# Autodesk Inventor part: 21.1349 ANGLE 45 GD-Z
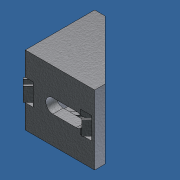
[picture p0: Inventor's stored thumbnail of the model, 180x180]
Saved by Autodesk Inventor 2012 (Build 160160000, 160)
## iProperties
Created: 2007-01
Part Number: 21.1349 ANGLE 45 GD-Z
Document SubType Name: Modeling
Designer: Andy Moles
Material: Aluminum-6061
Mass: 60.029 g
Surface Area: 98.9545 cm^2
Volume: 22.1509 cm^3
Density: 2.71 g/cm^3
Author: Andy Moles
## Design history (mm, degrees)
sketch "Sketch1"
  geometry: L1 (0, 0)-(0, 40); L2 (0, 0)-(40, 0); L3 (40, 0)-(40, 6); L4 (0, 40)-(6, 40); L5 (40, 6)-(6, 40)
  constraints: 10 end point, 3 perpendicular, 1 vertical
  dimensions: "d0" = 40 distance of L1.start L1.end; "d1" = 40 distance of L1.start L2.end; "d2" = 6 distance of L1.end L4.end; "d3" = 6 distance of L2.end L3.end
extrude "Extrusion1" new body sketch "Sketch1" stored distance "d4" = 40; taper "d5" = 0 deg
workplane "Work Plane1"
sketch "Sketch2"
  geometry: L1 (-20, 34)-(-20, 0) reference; L2 (-20, 0)-(20, 0) reference; L3 (20, 0)-(20, 34) reference; L4 (-20, 34)-(20, 34) reference; L5 (-14.5, 34)-(14.5, 34); L6 (14.5, 34)-(14.5, 0); L7 (14.5, 0)-(-14.5, 0); L8 (-14.5, 0)-(-14.5, 34); 1 further point
  constraints: 8 end point, 2 parallel, 2 point on line, 1 horizontal, 1 perpendicular
  dimensions: "d7" = 5.5 distance between parallel lines of L8 L1; "d8" = 5.5 distance between parallel lines of L3 L6
extrude "Extrusion2" cut sketch "Sketch2" stored distance "d9" = 40; taper "d10" = 0 deg
sketch "Sketch3"
  geometry: L1 (0, -14.5)-(0, 14.5) reference; L2 (-34, -20)-(0, -20) reference; L3 (-24.1, 4.1)-(-10.6, 4.1); L4 (-10.6, -4.1)-(-24.1, -4.1); A1 r 4.1 centre (-24.1, 0) between (-24.1, 4.1) and (-24.1, -4.1); A2 r 4.1 centre (-10.6, 0) between (-10.6, -4.1) and (-10.6, 4.1); 1 further point
  constraints: 4 end point, 4 point on circle, 3 tangent, 2 centre point, 1 horizontal alignment, 1 parallel
  dimensions: "d11" = 8.2 diameter of A1; "d12" = 8.2 diameter of A2; "d13" = 13.5 distance of A1.centre A2.centre; "d14" = 20 distance from line of A2.centre L2; "d15" = 6.5 distance edge to line of A2 L1
extrude "Extrusion3" cut sketch "Sketch3" stored distance "d16" = 40; taper "d17" = 0 deg
sketch "Sketch4"
  geometry: L1 (0, 34)-(29, 34) reference; L2 (29, 0)-(29, 34) reference; L3 (18.6, 23.4)-(18.6, 9.9); L4 (10.4, 23.4)-(10.4, 9.9); L5 (34.5, 0)-(34.5, 34) reference; A1 r 4.1 centre (14.5, 9.9) between (10.4, 9.9) and (18.6, 9.9); A2 r 4.1 centre (14.5, 23.4) between (18.6, 23.4) and (10.4, 23.4); 1 further point
  constraints: 4 end point, 4 point on circle, 3 tangent, 2 centre point, 1 parallel, 1 vertical alignment
  dimensions: "d18" = 8.2 diameter of A1; "d19" = 8.2 diameter of A2; "d20" = 13.5 distance of A2.centre A1.centre; "d21" = 20 distance from line of A2.centre L5; "d22" = 6.5 distance edge to line of A2 L1
extrude "Extrusion4" cut sketch "Sketch4" stored distance "d23" = 40; taper "d24" = 0 deg
workplane "Work Plane2"
sketch "Sketch5"
  geometry: L1 (40, 0)-(0, 0) reference; L2 (0, 0)-(4.5, 0); L3 (4.5, 0)-(0, 4.5); L4 (0, 4.5)-(0, 0); L5 (38.182, 0)-(35, 3.182); L6 (35, 3.182)-(31.818, 0); L7 (40, 6)-(40, 0) reference; L8 (0, 0)-(0, 40) reference; L9 (0, 38.182)-(3.182, 35); L10 (3.182, 35)-(0, 31.818); L11 (0, 40)-(6, 40) reference
  constraints: 14 end point, 5 perpendicular, 5 point on line, 1 parallel
  dimensions: "d25" = 4.5 distance of L1.end L2.end; "d26" = 4.5 distance of L5.start L5.end; "d27" = 5 distance from line of L5.end L7; "d28" = 4.5 distance of L9.end L10.end; "d29" = 5 distance from line of L9.end L11
extrude "Extrusion5" cut sketch "Sketch5" stored distance "d30" = 12.7; taper "d31" = 0 deg
sketch "Sketch6"
  geometry: L1 (4.5, 12.7)-(4.5, 0) reference; L2 (4.3, 2.25)-(3.1, 2.25); L3 (3.1, 2.25)-(3.1, 10.45); L4 (3.1, 10.45)-(4.3, 10.45); L5 (4.3, 10.45)-(4.3, 2.25); 3 further points
  constraints: 8 end point, 2 midpoint, 2 parallel, 1 horizontal, 1 horizontal alignment, 1 perpendicular
  dimensions: "d32" = 8.2 distance of L2.end L3.end; "d33" = 1.2 distance of L3.end L4.end; "d34" = 0.2 distance between parallel lines of L1 L5
extrude "Extrusion6" join sketch "Sketch6" distance "d35" = 4; taper "d36" = 0 deg
sketch "Sketch7"
  geometry: L1 (-5.817, 12.7)-(-5.817, 0); L2 (-6.017, 2.25)-(-7.217, 2.25); L3 (-7.217, 2.25)-(-7.217, 10.45); L4 (-7.217, 10.45)-(-6.017, 10.45); L5 (-6.017, 10.45)-(-6.017, 2.25); L6 (-5.817, 12.7)-(-5.817, 0) reference; 3 further points
  constraints: 10 end point, 2 midpoint, 2 parallel, 1 collinear, 1 horizontal, 1 horizontal alignment, 1 perpendicular
  dimensions: "d39" = 8.2 distance of L2.end L3.end; "d38" = 1.2 distance of L3.end L4.end; "d37" = 0.2 distance between parallel lines of L1 L5
extrude "Extrusion7" join sketch "Sketch7" taper "d41" = 0 deg; distance "d42" = 4
sketch "Sketch8"
  geometry: L1 (-5.168, 12.119)-(-5.168, 0); L2 (-5.368, 1.96)-(-6.568, 1.96); L3 (-6.568, 1.96)-(-6.568, 10.16); L4 (-6.568, 10.16)-(-5.368, 10.16); L5 (-5.368, 10.16)-(-5.368, 1.96); L6 (-5.168, 12.7)-(-5.168, 0); L7 (-10.132, 1.96)-(-11.332, 1.96) reference; L8 (-5.168, 12.41)-(-5.168, -0.29) reference; 3 further points
  constraints: 12 end point, 3 collinear, 2 midpoint, 2 parallel, 1 horizontal, 1 horizontal alignment, 1 perpendicular
  dimensions: "d45" = 8.2 distance of L2.end L3.end; "d44" = 1.2 distance of L3.end L4.end; "d43" = 0.2 distance between parallel lines of L1 L5
extrude "Extrusion8" join sketch "Sketch8" taper "d47" = 0 deg; distance "d48" = 4
sketch "Sketch9"
  geometry: L1 (-5.386, 12.454)-(-5.386, 0); L2 (-5.586, 2.127)-(-6.786, 2.127); L3 (-6.786, 2.127)-(-6.786, 10.327); L4 (-6.786, 10.327)-(-5.586, 10.327); L5 (-5.586, 10.327)-(-5.586, 2.127); L6 (-5.386, 12.7)-(-5.386, 0); L7 (-5.386, 12.577)-(-5.386, -0.123) reference; 3 further points
  constraints: 12 end point, 3 midpoint, 2 parallel, 1 collinear, 1 horizontal, 1 horizontal alignment, 1 perpendicular
  dimensions: "d51" = 8.2 distance of L2.end L3.end; "d50" = 1.2 distance of L3.end L4.end; "d49" = 0.2 distance between parallel lines of L1 L5
extrude "Extrusion9" join sketch "Sketch9" taper "d53" = 0 deg; distance "d54" = 4
sketch "Sketch10"
  geometry: L1 (34, 0)-(0, 0); L2 (0, 0)-(0, 34); L3 (0, 34)-(34, 0); L4 (0, 0)-(17, 17); L5 (0, 5.303)-(13.464, 18.768); L6 (0, 1.768)-(15.232, 17); L7 (0, 5.303)-(0, 1.768); L8 (5.303, 0)-(1.768, 0); L9 (5.303, 0)-(18.768, 13.464); L10 (1.768, 0)-(17, 15.232); A1 r 1.25 centre (14.348, 17.884) between (15.232, 17) and (13.464, 18.768); A2 r 1.25 centre (17.884, 14.348) between (18.768, 13.464) and (17, 15.232); 1 further point
  constraints: 20 end point, 5 symmetric about line, 4 point on circle, 2 centre point, 2 point on line, 2 tangent, 1 midpoint, 1 parallel, 1 perpendicular, 1 other
  dimensions: "d55" = 2.5 distance between parallel lines of L6 L5; "d56" = 1.25 distance between parallel lines of L4 L6; "d57" = 2.5 diameter of A1
extrude "Extrusion10" join sketch "Sketch10" distance "d58" = 1; taper "d59" = 0 deg
mirror "Mirror1"
body "Solid1"
node "Projected Loop1"
other parameters: "d6" = 90 deg
